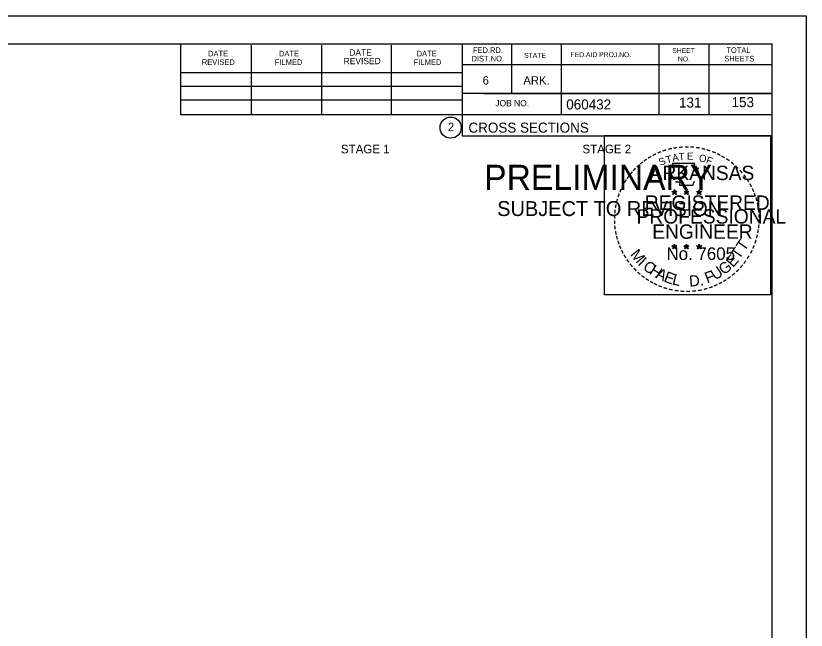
# Model space of a CAD drawing. Extents: x 1538688 to 1540766, y 656250 to 671912.
# Drawn here: x 1538911.1 to 1539021.1, y 668412.7 to 668498.2 of the extents above; entities that cross this region are included whole.
import ezdxf

# ---------------------------------------------------------------- set-up
doc = ezdxf.new("R2010")
doc.units = 0
for name, color, linetype in [('26', 7, 'Continuous'), ('7', 7, 'Continuous'), ('8', 7, 'Continuous'), ('9', 7, 'Continuous'), ('Default', 7, 'Continuous'), ('RipRap', 7, 'Continuous')]:
    doc.layers.add(name, color=color, linetype=linetype)

msp = doc.modelspace()

# ---------------------------------------------------------------- linework, layer by layer
at = {"layer": '26'}
msp.add_line((1538687.78, 668498.16), (1539021.11, 668498.16), dxfattribs=at)
for points in [[(1538687.77, 668498.16), (1539021.11, 668498.16), (1539021.11, 668284.83), (1538687.77, 668284.83)], [(1538993.03, 668481.5), (1539016.13, 668481.5), (1539016.13, 668459.35), (1538993.03, 668459.35)]]:
    msp.add_lwpolyline(points, close=True, dxfattribs=at)
at = {"layer": '8'}
for p, q in [((1539002.44, 668473.71), (1539002.79, 668473.6)), ((1539002.44, 668473.71), (1539002.69, 668473.67)), ((1539002.44, 668473.71), (1539002.68, 668473.59)), ((1539002.57, 668473.31), (1539002.79, 668473.6)), ((1539002.57, 668473.31), (1539002.7, 668473.55)), ((1539002.57, 668473.31), (1539002.79, 668473.52)), ((1539002.79, 668473.97), (1539002.75, 668473.72)), ((1539002.79, 668473.6), (1539002.79, 668473.97)), ((1539002.79, 668473.97), (1539002.84, 668473.72)), ((1539003.13, 668473.71), (1539002.79, 668473.6)), ((1539003, 668473.31), (1539002.79, 668473.6)), ((1539003, 668473.31), (1539002.79, 668473.52)), ((1539003.13, 668473.71), (1539002.85, 668473.67)), ((1539003, 668473.31), (1539002.86, 668473.6)), ((1539003.13, 668473.71), (1539002.93, 668473.61)), ((1539004.11, 668473.71), (1539004.46, 668473.6)), ((1539004.11, 668473.71), (1539004.36, 668473.67)), ((1539004.11, 668473.71), (1539004.35, 668473.59)), ((1539004.24, 668473.31), (1539004.46, 668473.6)), ((1539004.24, 668473.31), (1539004.37, 668473.55)), ((1539004.24, 668473.31), (1539004.46, 668473.52)), ((1539004.46, 668473.97), (1539004.42, 668473.72)), ((1539004.46, 668473.6), (1539004.46, 668473.97)), ((1539004.46, 668473.97), (1539004.51, 668473.72)), ((1539004.8, 668473.71), (1539004.46, 668473.6)), ((1539004.67, 668473.31), (1539004.46, 668473.6)), ((1539004.67, 668473.31), (1539004.46, 668473.52)), ((1539004.8, 668473.71), (1539004.52, 668473.67)), ((1539004.67, 668473.31), (1539004.53, 668473.6)), ((1539004.8, 668473.71), (1539004.6, 668473.61)), ((1539005.87, 668473.7), (1539006.22, 668473.59)), ((1539005.87, 668473.7), (1539006.13, 668473.66)), ((1539005.87, 668473.7), (1539006.11, 668473.58)), ((1539006.01, 668473.29), (1539006.22, 668473.59)), ((1539006.01, 668473.29), (1539006.13, 668473.54)), ((1539006.01, 668473.29), (1539006.22, 668473.51)), ((1539006.22, 668473.96), (1539006.18, 668473.7)), ((1539006.22, 668473.59), (1539006.22, 668473.96)), ((1539006.22, 668473.96), (1539006.27, 668473.71)), ((1539006.57, 668473.7), (1539006.22, 668473.59)), ((1539006.43, 668473.29), (1539006.22, 668473.59)), ((1539006.43, 668473.29), (1539006.22, 668473.51)), ((1539006.57, 668473.7), (1539006.28, 668473.65)), ((1539006.43, 668473.29), (1539006.3, 668473.59)), ((1539006.57, 668473.7), (1539006.36, 668473.6)), ((1539002.78, 668466.4), (1539002.74, 668466.14)), ((1539002.78, 668466.03), (1539002.78, 668466.4)), ((1539002.78, 668466.4), (1539002.83, 668466.15)), ((1539004.45, 668466.4), (1539004.41, 668466.14)), ((1539004.45, 668466.03), (1539004.45, 668466.4)), ((1539004.45, 668466.4), (1539004.5, 668466.15)), ((1539006.22, 668466.39), (1539006.18, 668466.13)), ((1539006.22, 668466.02), (1539006.22, 668466.39)), ((1539006.22, 668466.39), (1539006.27, 668466.14)), ((1539002.43, 668466.14), (1539002.78, 668466.03)), ((1539002.43, 668466.14), (1539002.69, 668466.1)), ((1539002.43, 668466.14), (1539002.67, 668466.02)), ((1539002.57, 668465.73), (1539002.78, 668466.03)), ((1539002.57, 668465.73), (1539002.69, 668465.98)), ((1539002.57, 668465.73), (1539002.78, 668465.95)), ((1539003.13, 668466.14), (1539002.78, 668466.03)), ((1539003, 668465.73), (1539002.78, 668466.03)), ((1539003, 668465.73), (1539002.78, 668465.95)), ((1539003.13, 668466.14), (1539002.84, 668466.09)), ((1539003, 668465.73), (1539002.86, 668466.02)), ((1539003.13, 668466.14), (1539002.93, 668466.04)), ((1539004.1, 668466.14), (1539004.45, 668466.03)), ((1539004.1, 668466.14), (1539004.36, 668466.1)), ((1539004.1, 668466.14), (1539004.34, 668466.02)), ((1539004.24, 668465.73), (1539004.45, 668466.03)), ((1539004.24, 668465.73), (1539004.36, 668465.98)), ((1539004.24, 668465.73), (1539004.45, 668465.95)), ((1539004.8, 668466.14), (1539004.45, 668466.03)), ((1539004.67, 668465.73), (1539004.45, 668466.03)), ((1539004.67, 668465.73), (1539004.45, 668465.95)), ((1539004.8, 668466.14), (1539004.51, 668466.09)), ((1539004.67, 668465.73), (1539004.53, 668466.02)), ((1539004.8, 668466.14), (1539004.6, 668466.04)), ((1539005.87, 668466.13), (1539006.22, 668466.02)), ((1539005.87, 668466.13), (1539006.12, 668466.09)), ((1539005.87, 668466.13), (1539006.11, 668466.01)), ((1539006, 668465.72), (1539006.22, 668466.02)), ((1539006, 668465.72), (1539006.13, 668465.97)), ((1539006, 668465.72), (1539006.22, 668465.94)), ((1539006.57, 668466.13), (1539006.22, 668466.02)), ((1539006.43, 668465.72), (1539006.22, 668466.02)), ((1539006.43, 668465.72), (1539006.22, 668465.94)), ((1539006.57, 668466.13), (1539006.28, 668466.08)), ((1539006.43, 668465.72), (1539006.3, 668466.01)), ((1539006.57, 668466.13), (1539006.36, 668466.03))]:
    msp.add_line(p, q, dxfattribs=at)
for points in [[(1539002.48, 668477.59), (1539002.75, 668476.77)], [(1539005.99, 668476.67), (1539006.13, 668476.95), (1539005.45, 668476.93), (1539005.6, 668477.59), (1539002.48, 668477.59)], [(1539002.97, 668475.17), (1539002.97, 668475.08), (1539003.53, 668475.06), (1539003.48, 668474.59), (1539005.35, 668474.59), (1539005.55, 668475.13)], [(1539002.79, 668473.97), (1539003, 668473.31), (1539002.44, 668473.71), (1539003.13, 668473.71), (1539002.57, 668473.31), (1539002.79, 668473.97)], [(1539004.46, 668473.97), (1539004.67, 668473.31), (1539004.11, 668473.71), (1539004.8, 668473.71), (1539004.24, 668473.31), (1539004.46, 668473.97)], [(1539006.22, 668473.96), (1539006.43, 668473.29), (1539005.87, 668473.7), (1539006.57, 668473.7), (1539006.01, 668473.29), (1539006.22, 668473.96)], [(1539002.78, 668466.4), (1539003, 668465.73), (1539002.43, 668466.14), (1539003.13, 668466.14), (1539002.57, 668465.73), (1539002.78, 668466.4)], [(1539004.45, 668466.4), (1539004.67, 668465.73), (1539004.1, 668466.14), (1539004.8, 668466.14), (1539004.24, 668465.73), (1539004.45, 668466.4)], [(1539006.22, 668466.39), (1539006.43, 668465.72), (1539005.87, 668466.13), (1539006.57, 668466.13), (1539006, 668465.72), (1539006.22, 668466.39)]]:
    msp.add_lwpolyline(points, dxfattribs=at)
for centre, radius in [((1539002.79, 668473.6), 0.172), ((1539002.79, 668473.6), 0.145), ((1539002.79, 668473.6), 0.116), ((1539002.79, 668473.6), 0.0991), ((1539002.79, 668473.6), 0.0747), ((1539002.79, 668473.6), 0.0495), ((1539002.79, 668473.6), 0.0296), ((1539004.46, 668473.6), 0.172), ((1539004.46, 668473.6), 0.145), ((1539004.46, 668473.6), 0.116), ((1539004.46, 668473.6), 0.0991), ((1539004.46, 668473.6), 0.0747), ((1539004.46, 668473.6), 0.0495), ((1539004.46, 668473.6), 0.0296), ((1539006.22, 668473.59), 0.172), ((1539006.22, 668473.59), 0.145), ((1539006.22, 668473.59), 0.116), ((1539006.22, 668473.59), 0.0991), ((1539006.22, 668473.59), 0.0747), ((1539006.22, 668473.59), 0.0495), ((1539006.22, 668473.59), 0.0296), ((1539002.78, 668466.03), 0.172), ((1539002.78, 668466.03), 0.145), ((1539002.78, 668466.03), 0.116), ((1539002.78, 668466.03), 0.0991), ((1539002.78, 668466.03), 0.0747), ((1539002.78, 668466.03), 0.0495), ((1539002.78, 668466.03), 0.0296), ((1539004.45, 668466.03), 0.172), ((1539004.45, 668466.03), 0.145), ((1539004.45, 668466.03), 0.116), ((1539004.45, 668466.03), 0.0991), ((1539004.45, 668466.03), 0.0747), ((1539004.45, 668466.03), 0.0495), ((1539004.45, 668466.03), 0.0296), ((1539006.22, 668466.02), 0.172), ((1539006.22, 668466.02), 0.145), ((1539006.22, 668466.02), 0.116), ((1539006.22, 668466.02), 0.0991), ((1539006.22, 668466.02), 0.0747), ((1539006.22, 668466.02), 0.0495), ((1539006.22, 668466.02), 0.0296)]:
    msp.add_circle(centre, radius, dxfattribs=at)
at = {"layer": 'RipRap'}
for p, q in [((1538700.18, 668494.27), (1539016.36, 668494.27)), ((1538934.1, 668484.39), (1538934.1, 668494.27)), ((1538943.96, 668484.39), (1538943.96, 668494.07)), ((1538953.72, 668484.39), (1538953.72, 668494.07)), ((1538963.4, 668484.39), (1538963.4, 668494.07)), ((1538973.26, 668494.27), (1538973.26, 668481.47)), ((1538980.1, 668494.27), (1538980.1, 668487.33)), ((1538987.04, 668494.27), (1538987.04, 668484.39)), ((1539000.62, 668494.27), (1539000.62, 668484.39)), ((1539007.56, 668494.27), (1539007.56, 668484.39)), ((1539016.36, 668288.81), (1539016.36, 668494.27)), ((1539016.36, 668491.33), (1538973.26, 668491.33)), ((1539016.36, 668491.35), (1539016.36, 668491.35)), ((1538934.1, 668490.25), (1538973.26, 668490.25)), ((1538934.1, 668488.39), (1538973.26, 668488.39)), ((1539016.36, 668487.33), (1538973.26, 668487.33)), ((1538976.22, 668487.33), (1539016.36, 668487.33)), ((1538934.1, 668484.39), (1538934.1, 668486.45)), ((1538934.1, 668486.45), (1538973.26, 668486.45)), ((1539016.36, 668484.39), (1538934.1, 668484.39)), ((1538973.26, 668481.47), (1539016.36, 668481.47))]:
    msp.add_line(p, q, dxfattribs=at)
msp.add_circle((1538971.64, 668482.6), 1.47, dxfattribs=at)

# ---------------------------------------------------------------- texts
at = {"layer": '7'}
for s, p in [('131', (1539003.41, 668485.39)), ('153', (1539010.73, 668485.45))]:
    msp.add_text(s, height=1.4, dxfattribs=at).set_placement(p)
at = {"layer": '8'}
for s, height, rotation, p in [('-', 1.6, 19.1761, (1539001.23, 668478.72)), ('-', 1.6, 13.6301, (1539001.98, 668478.96)), ('-', 1.6, 10.2193, (1539002.66, 668479.12)), ('-', 1.6, 5.8968, (1539003.38, 668479.23)), ('-', 1.6, 0.1862, (1539004.16, 668479.3)), ('-', 1.6, 357.743, (1539004.88, 668479.29)), ('-', 1.6, 352.1617, (1539005.62, 668479.24)), ('-', 1.6, 347.2049, (1539006.34, 668479.12)), ('-', 1.6, 342.3362, (1539006.98, 668478.97)), ('-', 1.6, 34.0636, (1538999.36, 668477.76)), ('-', 1.6, 28.7918, (1538999.96, 668478.13)), ('-', 1.6, 24.3072, (1539000.59, 668478.45)), ('S', 1, 21.594, (1539000.83, 668477.27)), ('T', 1, 16.4036, (1539001.75, 668477.6)), ('A', 1, 11.2132, (1539002.57, 668477.85)), ('T', 1, 6.0228, (1539003.42, 668478.02)), ('E', 1, 0.8323, (1539004.53, 668478.13)), ('O', 1, 350.4515, (1539006.13, 668477.92)), ('F', 1, 340.0707, (1539007.09, 668477.69)), ('-', 1.6, 337.8551, (1539007.71, 668478.74)), ('-', 1.6, 334.1211, (1539008.34, 668478.47)), ('-', 1.6, 329.6409, (1539008.92, 668478.19)), ('-', 1.6, 42.9622, (1538997.88, 668476.57)), ('-', 1.6, 38.9507, (1538998.31, 668476.99)), ('-', 1.6, 36.2317, (1538998.79, 668477.37)), ('ARKANSAS', 2, 360, (1538999.33, 668475.3)), ('-', 1.6, 325.8627, (1539009.57, 668477.83)), ('-', 1.6, 320.5297, (1539010.18, 668477.4)), ('-', 1.6, 315.5786, (1539010.77, 668476.91)), ('-', 1.6, 50.6142, (1538997.03, 668475.61)), ('-', 1.6, 48.423, (1538997.43, 668476.1)), ('-', 1.6, 309.8797, (1539011.34, 668476.36)), ('-', 1.6, 58.0706, (1538996.29, 668474.52)), ('-', 1.6, 54.2325, (1538996.61, 668475.04)), ('-', 1.6, 306.6522, (1539011.87, 668475.76)), ('-', 1.4, 303.6753, (1539012.35, 668475.19)), ('-', 1.6, 67.7743, (1538995.72, 668473.29)), ('-', 1.6, 62.8713, (1538995.97, 668473.9)), ('-', 1.6, 299.6684, (1539012.67, 668474.59)), ('-', 1.6, 294.6628, (1539013, 668473.98)), ('-', 1.6, 72.3945, (1538995.5, 668472.66)), ('REGISTERED', 2, 360, (1538998.65, 668471.16)), ('DWB', 0.01, 360, (1539002.77, 668473.6)), ('DWB', 0.01, 360, (1539004.44, 668473.6)), ('DWB', 0.01, 360, (1539006.21, 668473.59)), ('-', 1.6, 290.5728, (1539013.25, 668473.4)), ('-', 1.6, 285.1233, (1539013.49, 668472.82)), ('-', 1.6, 81.2013, (1538995.17, 668471.23)), ('-', 1.6, 75.461, (1538995.3, 668471.95)), ('-', 1.6, 280.5493, (1539013.69, 668472.08)), ('-', 1.6, 85.1863, (1538995.09, 668470.54)), ('PROFESSIONAL', 2, 360, (1538997.51, 668469.25)), ('-', 1.6, 276.5962, (1539013.85, 668471.31)), ('-', 1.6, 94.1959, (1538995.1, 668469.12)), ('-', 1.6, 89.0622, (1538995.07, 668469.84)), ('-', 1.6, 274.3301, (1539013.91, 668470.59)), ('-', 1.6, 269.9407, (1539013.94, 668469.95)), ('-', 1.6, 98.9479, (1538995.17, 668468.45)), ('ENGINEER', 2, 360, (1538999.69, 668467.13)), ('-', 1.6, 263.5172, (1539013.93, 668469.29)), ('-', 1.6, 101.7149, (1538995.31, 668467.72)), ('-', 1.6, 105.4578, (1538995.47, 668467.12)), ('-', 1.6, 255.7626, (1539013.74, 668467.96)), ('-', 1.6, 260.9953, (1539013.85, 668468.63)), ('-', 1.6, 109.0874, (1538995.69, 668466.49)), ('T', 1.54, 55.055, (1539012.5, 668465.3)), ('-', 1.6, 252.8681, (1539013.56, 668467.24)), ('-', 1.6, 114.0643, (1538995.94, 668465.89)), ('-', 1.6, 115.7289, (1538996.24, 668465.28)), ('M', 1.54, 308.9175, (1538996.55, 668464.92)), ('No. 7605', 1.757, 360, (1539001.67, 668464.18)), ('DWB', 0.01, 360, (1539002.77, 668466.03)), ('DWB', 0.01, 360, (1539004.44, 668466.02)), ('DWB', 0.01, 360, (1539006.2, 668466.02)), ('T', 1.54, 55.055, (1539011.77, 668464.18)), ('-', 1.6, 244.6197, (1539013.08, 668465.93)), ('-', 1.6, 247.8887, (1539013.34, 668466.56)), ('-', 1.6, 120.4471, (1538996.6, 668464.69)), ('-', 1.6, 125.8934, (1538997, 668464.13)), ('I', 1.54, 316.4636, (1538997.6, 668463.6)), ('E', 1.54, 48.7313, (1539010.93, 668463.05)), ('-', 1.6, 233.8452, (1539012.28, 668464.53)), ('-', 1.6, 239.0712, (1539012.68, 668465.18)), ('-', 1.6, 130.7181, (1538997.47, 668463.58)), ('-', 1.6, 134.2238, (1538997.98, 668463.03)), ('C', 1.54, 324.0197, (1538998.27, 668462.98)), ('H', 1.54, 327.5342, (1538999.18, 668462.32)), ('U', 1.54, 34.4052, (1539008.47, 668461.3)), ('G', 1.54, 38.2173, (1539009.67, 668462.03)), ('-', 1.6, 231.2538, (1539011.85, 668463.96)), ('-', 1.6, 138.9338, (1538998.51, 668462.57)), ('-', 1.6, 144.6463, (1538999.06, 668462.16)), ('A', 1.54, 332.5513, (1539000.03, 668461.79)), ('E', 1.54, 339.2068, (1539001.19, 668461.22)), ('L', 1.54, 346.2929, (1539002.38, 668460.8)), ('D.', 1.54, 5.2602, (1539004.89, 668460.46)), ('F', 1.54, 20.8202, (1539007.34, 668460.9)), ('-', 1.6, 215.7363, (1539010.3, 668462.42)), ('-', 1.6, 221.0851, (1539010.85, 668462.89)), ('-', 1.6, 225.7653, (1539011.37, 668463.4)), ('-', 1.6, 148.0898, (1538999.63, 668461.79)), ('-', 1.6, 151.5704, (1539000.2, 668461.47)), ('-', 1.6, 154.6002, (1539000.73, 668461.22)), ('-', 1.6, 204.2516, (1539008.59, 668461.37)), ('-', 1.6, 207.3568, (1539009.21, 668461.69)), ('-', 1.6, 212.2491, (1539009.77, 668462.03)), ('-', 1.6, 158.5612, (1539001.35, 668460.97)), ('-', 1.6, 162.7983, (1539002.04, 668460.75)), ('-', 1.6, 167.5555, (1539002.75, 668460.59)), ('-', 1.6, 173.1155, (1539003.52, 668460.48)), ('-', 1.6, 176.5183, (1539004.27, 668460.43)), ('-', 1.6, 181.5918, (1539005.02, 668460.44)), ('-', 1.6, 185.8167, (1539005.83, 668460.52)), ('-', 1.6, 191.2858, (1539006.56, 668460.65)), ('-', 1.6, 195.4743, (1539007.29, 668460.85)), ('-', 1.6, 200.7184, (1539007.97, 668461.09))]:
    msp.add_text(s, height=height, rotation=rotation, dxfattribs=at).set_placement(p)
at = {"layer": '9'}
for s, height, p in [('PRELIMINARY', 3.5, (1538976.31, 668473.93)), ('DWB', 0.01, (1538977.06, 668475.78)), ('SUBJECT TO REVISION', 2.0751, (1538978.12, 668470.3))]:
    msp.add_text(s, height=height, rotation=360, dxfattribs=at).set_placement(p)
at = {"layer": 'Default'}
for s, p in [('STAGE 1', (1538956.38, 668479.02)), ('STAGE 2', (1538989.98, 668479.02))]:
    msp.add_text(s, height=1.2, dxfattribs=at).set_placement(p)
at = {"layer": 'RipRap'}
for s, height, p in [('DATE', 0.782, (1538937.9, 668492.51)), ('DATE', 0.782, (1538947.76, 668492.51)), ('DATE', 0.879, (1538957.54, 668492.61)), ('DATE', 0.782, (1538966.92, 668492.51)), ('FED.RD.', 0.782, (1538974.74, 668492.99)), ('STATE', 0.684, (1538981.86, 668492.31)), ('FED.AID PROJ.NO.', 0.684, (1538988.32, 668492.41)), ('SHEET', 0.684, (1539002.48, 668492.99)), ('TOTAL', 0.782, (1539010, 668492.99)), ('REVISED', 0.782, (1538937.02, 668491.33)), ('FILMED', 0.782, (1538947.18, 668491.33)), ('REVISED', 0.879, (1538956.76, 668491.43)), ('FILMED', 0.782, (1538966.52, 668491.33)), ('DIST.NO.', 0.782, (1538974.54, 668491.81)), ('NO.', 0.684, (1539003.26, 668491.81)), ('SHEETS', 0.782, (1539009.72, 668491.81)), ('6', 1.17, (1538976.1, 668488.59)), ('ARK.', 1.172, (1538981.76, 668488.59)), ('JOB NO.', 0.879, (1538977.86, 668485.57)), ('060432', 1.4, (1538987.73, 668485.13)), ('2', 1.17, (1538971.26, 668482.12)), ('CROSS SECTIONS', 1.4, (1538974.12, 668481.9))]:
    msp.add_text(s, height=height, rotation=360, dxfattribs=at).set_placement(p)

doc.saveas('drawing.dxf')
